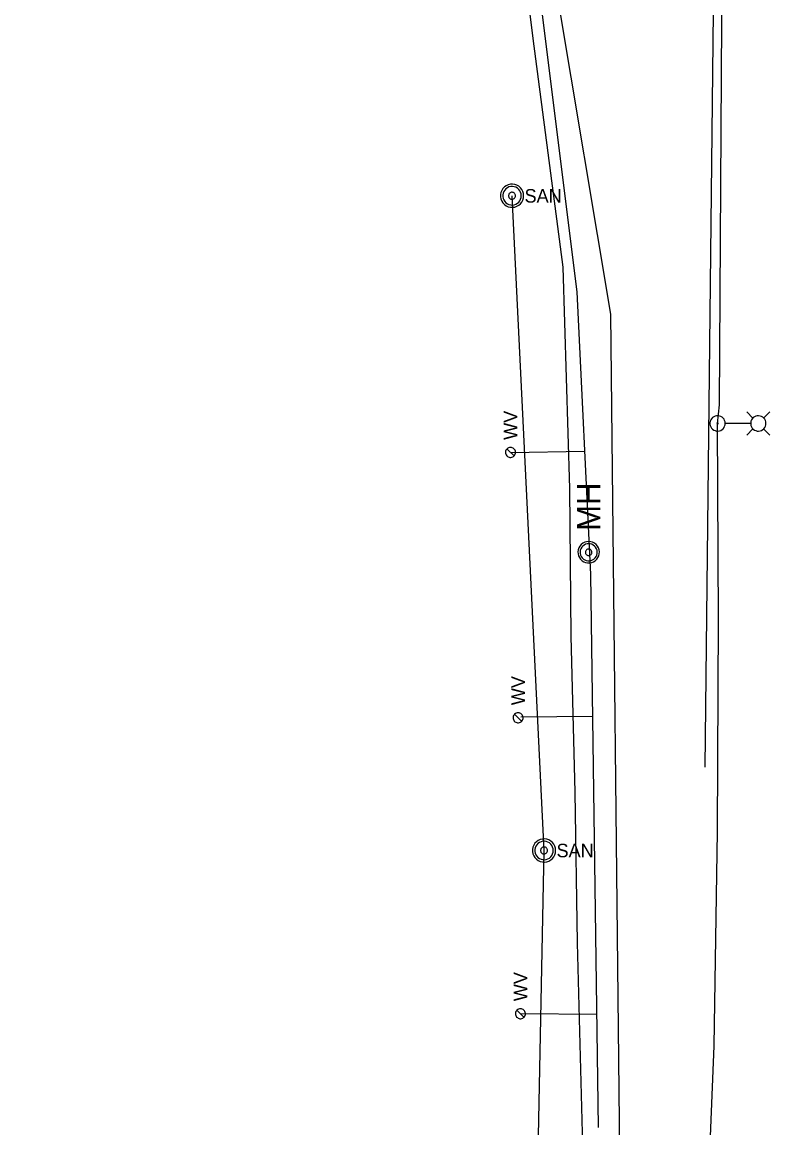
# Model space of a CAD drawing. Extents: x 600849 to 606371, y 330010 to 403088.
# Drawn here: x 604680.9 to 604893.9, y 332049.2 to 332364 of the extents above; entities that cross this region are included whole.
import ezdxf

# ---------------------------------------------------------------- set-up
doc = ezdxf.new("R2010")
doc.units = 0
for name, color, linetype in [('E_FTMS_Conduit', 7, 'Continuous'), ('E_LTG', 7, 'Continuous'), ('E_LTG_CID', 7, 'Continuous'), ('E_UTL_G_UG', 7, 'Continuous'), ('E_UTL_SAN', 7, 'Continuous'), ('E_UTL_SAN_UG', 7, 'Continuous'), ('E_UTL_W', 7, 'Continuous'), ('E_UTL_W_MH', 7, 'Continuous'), ('E_UTL_W_UG', 7, 'Continuous')]:
    doc.layers.add(name, color=color, linetype=linetype)

msp = doc.modelspace()

# ---------------------------------------------------------------- linework, layer by layer
at = {"layer": 'E_FTMS_Conduit'}
msp.add_lwpolyline([(604875.48, 332151.89), (604882.43, 332779.77)], dxfattribs=at)
at = {"layer": 'E_LTG'}
for points in [[(604889.11, 332251.25), (604887.33, 332253.03)], [(604892.15, 332251.25), (604893.93, 332253.03)], [(604881.2, 332249.73), (604881.16, 332250.14), (604881.04, 332250.54), (604880.86, 332250.9), (604880.6, 332251.23), (604880.29, 332251.5), (604879.93, 332251.71), (604879.54, 332251.84), (604879.13, 332251.9), (604878.72, 332251.88), (604878.31, 332251.78), (604877.94, 332251.61), (604877.6, 332251.37), (604877.31, 332251.07), (604877.09, 332250.72), (604876.94, 332250.34), (604876.86, 332249.93), (604876.86, 332249.52), (604876.94, 332249.11), (604877.09, 332248.73), (604877.31, 332248.38), (604877.6, 332248.08), (604877.94, 332247.84), (604878.31, 332247.67), (604878.72, 332247.57), (604879.13, 332247.55), (604879.54, 332247.61), (604879.93, 332247.75), (604880.29, 332247.96), (604880.6, 332248.23), (604880.86, 332248.55), (604881.04, 332248.92), (604881.16, 332249.32), (604881.2, 332249.73)], [(604879.19, 332249.73), (604879.19, 332249.76), (604879.18, 332249.79), (604879.17, 332249.82), (604879.15, 332249.84), (604879.12, 332249.86), (604879.09, 332249.88), (604879.06, 332249.89), (604879.03, 332249.89), (604879, 332249.89), (604878.97, 332249.88), (604878.94, 332249.87), (604878.92, 332249.85), (604878.89, 332249.83), (604878.88, 332249.8), (604878.87, 332249.77), (604878.86, 332249.74), (604878.86, 332249.71), (604878.87, 332249.68), (604878.88, 332249.65), (604878.89, 332249.62), (604878.92, 332249.6), (604878.94, 332249.58), (604878.97, 332249.57), (604879, 332249.56), (604879.03, 332249.56), (604879.06, 332249.57), (604879.09, 332249.58), (604879.12, 332249.59), (604879.15, 332249.61), (604879.17, 332249.64), (604879.18, 332249.67), (604879.19, 332249.7), (604879.19, 332249.73)], [(604888.42, 332249.73), (604881.24, 332249.73)], [(604892.8, 332249.73), (604892.76, 332250.14), (604892.65, 332250.54), (604892.46, 332250.9), (604892.2, 332251.23), (604891.89, 332251.5), (604891.53, 332251.71), (604891.14, 332251.84), (604890.73, 332251.9), (604890.32, 332251.88), (604889.92, 332251.78), (604889.54, 332251.61), (604889.2, 332251.37), (604888.92, 332251.07), (604888.69, 332250.72), (604888.54, 332250.34), (604888.46, 332249.93), (604888.46, 332249.52), (604888.54, 332249.11), (604888.69, 332248.73), (604888.92, 332248.38), (604889.2, 332248.08), (604889.54, 332247.84), (604889.92, 332247.67), (604890.32, 332247.57), (604890.73, 332247.55), (604891.14, 332247.61), (604891.53, 332247.75), (604891.89, 332247.96), (604892.2, 332248.23), (604892.46, 332248.55), (604892.65, 332248.92), (604892.76, 332249.32), (604892.8, 332249.73)], [(604889.11, 332248.21), (604887.33, 332246.43)], [(604892.15, 332248.21), (604893.93, 332246.43)]]:
    msp.add_lwpolyline(points, dxfattribs=at)
at = {"layer": 'E_LTG_CID'}
msp.add_lwpolyline([(604680.92, 331223.31), (604778.52, 331467.17), (604841.28, 331722.49), (604873.72, 331985.14), (604875.05, 331997.61), (604878.05, 332072.5), (604879.01, 332133.59), (604879.29, 332193.85), (604879.03, 332249.73), (604879.6, 332255.02), (604881.21, 332520.43)], dxfattribs=at)
at = {"layer": 'E_UTL_G_UG'}
msp.add_lwpolyline([(604775.55, 331850.28), (604782.88, 331849.84), (604813.11, 331848.32), (604833.71, 331846.3), (604837.08, 331886.64), (604839.03, 331930.43), (604839.41, 331959.55), (604839.41, 331985.27), (604840.59, 332047.8), (604839.11, 332101.83), (604838.47, 332144.72), (604837.35, 332189.15), (604836.96, 332231.16), (604835.01, 332294.2), (604826.46, 332359.31), (604815.87, 332444.5)], dxfattribs=at)
at = {"layer": 'E_UTL_SAN'}
for points in [[(604823.78, 332314.55), (604823.72, 332315.17), (604823.54, 332315.77), (604823.25, 332316.33), (604822.87, 332316.82), (604822.39, 332317.23), (604821.85, 332317.55), (604821.26, 332317.75), (604820.64, 332317.84), (604820.01, 332317.81), (604819.4, 332317.66), (604818.83, 332317.4), (604818.32, 332317.04), (604817.88, 332316.59), (604817.54, 332316.06), (604817.31, 332315.48), (604817.19, 332314.86), (604817.19, 332314.23), (604817.31, 332313.62), (604817.54, 332313.03), (604817.88, 332312.51), (604818.32, 332312.05), (604818.83, 332311.69), (604819.4, 332311.43), (604820.01, 332311.28), (604820.64, 332311.25), (604821.26, 332311.34), (604821.85, 332311.54), (604822.39, 332311.86), (604822.87, 332312.27), (604823.25, 332312.76), (604823.54, 332313.32), (604823.72, 332313.92), (604823.78, 332314.55)], [(604823.12, 332314.55), (604823.07, 332315.05), (604822.93, 332315.53), (604822.7, 332315.97), (604822.39, 332316.37), (604822.01, 332316.7), (604821.57, 332316.95), (604821.1, 332317.11), (604820.6, 332317.18), (604820.1, 332317.16), (604819.61, 332317.04), (604819.16, 332316.83), (604818.75, 332316.54), (604818.4, 332316.18), (604818.13, 332315.76), (604817.94, 332315.29), (604817.85, 332314.8), (604817.85, 332314.29), (604817.94, 332313.8), (604818.13, 332313.34), (604818.4, 332312.91), (604818.75, 332312.55), (604819.16, 332312.26), (604819.61, 332312.05), (604820.1, 332311.93), (604820.6, 332311.91), (604821.1, 332311.98), (604821.57, 332312.14), (604822.01, 332312.4), (604822.39, 332312.72), (604822.7, 332313.12), (604822.93, 332313.56), (604823.07, 332314.05), (604823.12, 332314.55)], [(604821.47, 332314.55), (604821.45, 332314.73), (604821.4, 332314.91), (604821.31, 332315.08), (604821.19, 332315.23), (604821.05, 332315.35), (604820.89, 332315.45), (604820.71, 332315.51), (604820.53, 332315.53), (604820.34, 332315.53), (604820.15, 332315.48), (604819.98, 332315.4), (604819.83, 332315.29), (604819.7, 332315.16), (604819.6, 332315), (604819.53, 332314.82), (604819.49, 332314.64), (604819.49, 332314.45), (604819.53, 332314.27), (604819.6, 332314.09), (604819.7, 332313.93), (604819.83, 332313.8), (604819.98, 332313.69), (604820.15, 332313.61), (604820.34, 332313.57), (604820.53, 332313.56), (604820.71, 332313.58), (604820.89, 332313.64), (604821.05, 332313.74), (604821.19, 332313.86), (604821.31, 332314.01), (604821.4, 332314.18), (604821.45, 332314.36), (604821.47, 332314.55)], [(604832.89, 332128.15), (604832.83, 332128.78), (604832.66, 332129.38), (604832.37, 332129.94), (604831.98, 332130.43), (604831.51, 332130.84), (604830.96, 332131.15), (604830.37, 332131.36), (604829.75, 332131.45), (604829.12, 332131.42), (604828.51, 332131.27), (604827.94, 332131.01), (604827.43, 332130.65), (604827, 332130.19), (604826.66, 332129.67), (604826.43, 332129.08), (604826.31, 332128.47), (604826.31, 332127.84), (604826.43, 332127.22), (604826.66, 332126.64), (604827, 332126.11), (604827.43, 332125.66), (604827.94, 332125.3), (604828.51, 332125.03), (604829.12, 332124.89), (604829.75, 332124.86), (604830.37, 332124.95), (604830.96, 332125.15), (604831.51, 332125.46), (604831.98, 332125.88), (604832.37, 332126.37), (604832.66, 332126.93), (604832.83, 332127.53), (604832.89, 332128.15)], [(604832.23, 332128.15), (604832.19, 332128.65), (604832.04, 332129.13), (604831.81, 332129.58), (604831.5, 332129.97), (604831.13, 332130.3), (604830.69, 332130.55), (604830.22, 332130.72), (604829.72, 332130.79), (604829.22, 332130.77), (604828.73, 332130.65), (604828.27, 332130.44), (604827.87, 332130.15), (604827.52, 332129.78), (604827.25, 332129.36), (604827.06, 332128.9), (604826.97, 332128.4), (604826.97, 332127.9), (604827.06, 332127.41), (604827.25, 332126.94), (604827.52, 332126.52), (604827.87, 332126.16), (604828.27, 332125.87), (604828.73, 332125.66), (604829.22, 332125.54), (604829.72, 332125.52), (604830.22, 332125.59), (604830.69, 332125.75), (604831.13, 332126), (604831.5, 332126.33), (604831.81, 332126.73), (604832.04, 332127.17), (604832.19, 332127.65), (604832.23, 332128.15)], [(604830.58, 332128.15), (604830.57, 332128.34), (604830.51, 332128.52), (604830.43, 332128.69), (604830.31, 332128.84), (604830.17, 332128.96), (604830.01, 332129.05), (604829.83, 332129.11), (604829.64, 332129.14), (604829.45, 332129.13), (604829.27, 332129.09), (604829.1, 332129.01), (604828.95, 332128.9), (604828.82, 332128.76), (604828.71, 332128.61), (604828.64, 332128.43), (604828.61, 332128.25), (604828.61, 332128.06), (604828.64, 332127.87), (604828.71, 332127.7), (604828.82, 332127.54), (604828.95, 332127.4), (604829.1, 332127.3), (604829.27, 332127.22), (604829.45, 332127.17), (604829.64, 332127.16), (604829.83, 332127.19), (604830.01, 332127.25), (604830.17, 332127.35), (604830.31, 332127.47), (604830.43, 332127.62), (604830.51, 332127.78), (604830.57, 332127.97), (604830.58, 332128.15)]]:
    msp.add_lwpolyline(points, dxfattribs=at)
at = {"layer": 'E_UTL_SAN_UG'}
for p, q in [((604829.59, 332128.15), (604820.48, 332314.54)), ((604824.4, 331859.94), (604829.59, 332128.15))]:
    msp.add_line(p, q, dxfattribs=at)
at = {"layer": 'E_UTL_W'}
for points in [[(604820.03, 332242.9), (604819.76, 332242.88), (604819.5, 332242.8), (604819.26, 332242.68), (604819.05, 332242.51), (604818.87, 332242.3), (604818.73, 332242.07), (604818.64, 332241.81), (604818.61, 332241.54), (604818.62, 332241.27), (604818.68, 332241.01), (604818.8, 332240.76), (604818.95, 332240.54), (604819.15, 332240.35), (604819.38, 332240.21), (604819.63, 332240.11), (604819.89, 332240.06), (604820.17, 332240.06), (604820.43, 332240.11), (604820.68, 332240.21), (604820.91, 332240.35), (604821.11, 332240.54), (604821.27, 332240.76), (604821.38, 332241.01), (604821.44, 332241.27), (604821.45, 332241.54), (604821.42, 332241.81), (604821.33, 332242.07), (604821.19, 332242.3), (604821.01, 332242.51), (604820.8, 332242.68), (604820.56, 332242.8), (604820.3, 332242.88), (604820.03, 332242.9)], [(604821.04, 332240.47), (604819.02, 332242.48)], [(604822.2, 332167.37), (604821.93, 332167.35), (604821.67, 332167.27), (604821.43, 332167.15), (604821.22, 332166.98), (604821.04, 332166.77), (604820.9, 332166.54), (604820.81, 332166.28), (604820.78, 332166.01), (604820.79, 332165.74), (604820.85, 332165.48), (604820.97, 332165.23), (604821.12, 332165.01), (604821.32, 332164.82), (604821.55, 332164.68), (604821.8, 332164.58), (604822.06, 332164.53), (604822.34, 332164.53), (604822.6, 332164.58), (604822.85, 332164.68), (604823.08, 332164.82), (604823.28, 332165.01), (604823.44, 332165.23), (604823.55, 332165.48), (604823.61, 332165.74), (604823.62, 332166.01), (604823.59, 332166.28), (604823.5, 332166.54), (604823.36, 332166.77), (604823.18, 332166.98), (604822.97, 332167.15), (604822.73, 332167.27), (604822.47, 332167.35), (604822.2, 332167.37)], [(604823.21, 332164.94), (604821.19, 332166.95)], [(604822.87, 332083.1), (604822.6, 332083.08), (604822.34, 332083), (604822.1, 332082.88), (604821.89, 332082.71), (604821.71, 332082.5), (604821.57, 332082.27), (604821.48, 332082.01), (604821.45, 332081.74), (604821.46, 332081.47), (604821.52, 332081.21), (604821.64, 332080.96), (604821.79, 332080.74), (604821.99, 332080.56), (604822.22, 332080.41), (604822.47, 332080.31), (604822.73, 332080.26), (604823.01, 332080.26), (604823.27, 332080.31), (604823.52, 332080.41), (604823.75, 332080.56), (604823.95, 332080.74), (604824.11, 332080.96), (604824.22, 332081.21), (604824.28, 332081.47), (604824.29, 332081.74), (604824.26, 332082.01), (604824.17, 332082.27), (604824.03, 332082.5), (604823.85, 332082.71), (604823.64, 332082.88), (604823.4, 332083), (604823.14, 332083.08), (604822.87, 332083.1)], [(604823.88, 332080.67), (604821.86, 332082.68)]]:
    msp.add_lwpolyline(points, dxfattribs=at)
at = {"layer": 'E_UTL_W_MH'}
for points in [[(604842.31, 332216.1), (604841.73, 332216.04), (604841.17, 332215.88), (604840.66, 332215.62), (604840.2, 332215.26), (604839.82, 332214.82), (604839.53, 332214.31), (604839.34, 332213.76), (604839.26, 332213.19), (604839.28, 332212.61), (604839.42, 332212.05), (604839.66, 332211.52), (604840, 332211.04), (604840.42, 332210.64), (604840.91, 332210.33), (604841.45, 332210.11), (604842.02, 332210), (604842.6, 332210), (604843.17, 332210.11), (604843.71, 332210.33), (604844.2, 332210.64), (604844.62, 332211.04), (604844.95, 332211.52), (604845.2, 332212.05), (604845.33, 332212.61), (604845.36, 332213.19), (604845.28, 332213.76), (604845.09, 332214.31), (604844.8, 332214.82), (604844.42, 332215.26), (604843.96, 332215.62), (604843.44, 332215.88), (604842.89, 332216.04), (604842.31, 332216.1)], [(604842.31, 332215.49), (604841.84, 332215.44), (604841.4, 332215.31), (604840.99, 332215.1), (604840.62, 332214.81), (604840.32, 332214.46), (604840.08, 332214.06), (604839.93, 332213.62), (604839.87, 332213.16), (604839.89, 332212.7), (604840, 332212.25), (604840.19, 332211.82), (604840.46, 332211.44), (604840.8, 332211.12), (604841.19, 332210.87), (604841.62, 332210.7), (604842.08, 332210.61), (604842.54, 332210.61), (604843, 332210.7), (604843.43, 332210.87), (604843.82, 332211.12), (604844.15, 332211.44), (604844.42, 332211.82), (604844.62, 332212.25), (604844.73, 332212.7), (604844.75, 332213.16), (604844.68, 332213.62), (604844.53, 332214.06), (604844.3, 332214.46), (604843.99, 332214.81), (604843.63, 332215.1), (604843.22, 332215.31), (604842.77, 332215.44), (604842.31, 332215.49)], [(604842.31, 332213.96), (604842.13, 332213.94), (604841.97, 332213.9), (604841.81, 332213.82), (604841.67, 332213.71), (604841.56, 332213.58), (604841.47, 332213.43), (604841.42, 332213.26), (604841.39, 332213.09), (604841.4, 332212.91), (604841.44, 332212.74), (604841.51, 332212.59), (604841.61, 332212.44), (604841.74, 332212.32), (604841.89, 332212.23), (604842.05, 332212.17), (604842.22, 332212.13), (604842.39, 332212.13), (604842.57, 332212.17), (604842.73, 332212.23), (604842.87, 332212.32), (604843, 332212.44), (604843.1, 332212.59), (604843.17, 332212.74), (604843.21, 332212.91), (604843.22, 332213.09), (604843.2, 332213.26), (604843.14, 332213.43), (604843.05, 332213.58), (604842.94, 332213.71), (604842.8, 332213.82), (604842.65, 332213.9), (604842.48, 332213.94), (604842.31, 332213.96)]]:
    msp.add_lwpolyline(points, dxfattribs=at)
at = {"layer": 'E_UTL_W_UG'}
for p, q in [((604848.64, 332280.87), (604812.41, 332497.24)), ((604839.02, 332287.19), (604828.93, 332367.61)), ((604842.95, 332206.74), (604839.02, 332287.19)), ((604853.09, 331867.44), (604848.64, 332280.87)), ((604845.11, 332049.33), (604842.95, 332206.74))]:
    msp.add_line(p, q, dxfattribs=at)
for points in [[(604820.03, 332241.48), (604841.23, 332241.87)], [(604843.5, 332166.28), (604822.95, 332166.13)], [(604844.67, 332081.42), (604822.87, 332081.68)]]:
    msp.add_lwpolyline(points, dxfattribs=at)

# ---------------------------------------------------------------- texts
at = {"layer": 'E_UTL_SAN'}
for p in [(604824.04, 332312.6), (604833.16, 332126.21)]:
    msp.add_text('SAN', height=3.849, dxfattribs=at).set_placement(p)
at = {"layer": 'E_UTL_W'}
for p in [(604821.96, 332245.04), (604824.13, 332169.51), (604824.8, 332085.24)]:
    msp.add_text('WV', height=3.85, rotation=90, dxfattribs=at).set_placement(p)
at = {"layer": 'E_UTL_W_MH'}
msp.add_text('MH', height=6.6, rotation=90, dxfattribs=at).set_placement((604845.61, 332219.16))

doc.saveas('drawing.dxf')
